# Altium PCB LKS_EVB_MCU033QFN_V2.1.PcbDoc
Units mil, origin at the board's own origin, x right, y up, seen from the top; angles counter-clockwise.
Board outline 2625 x 1560 mil, 2 copper layers (Top Layer, Bottom Layer); 25 components, 32 nets, 124 pads, 23 vias.
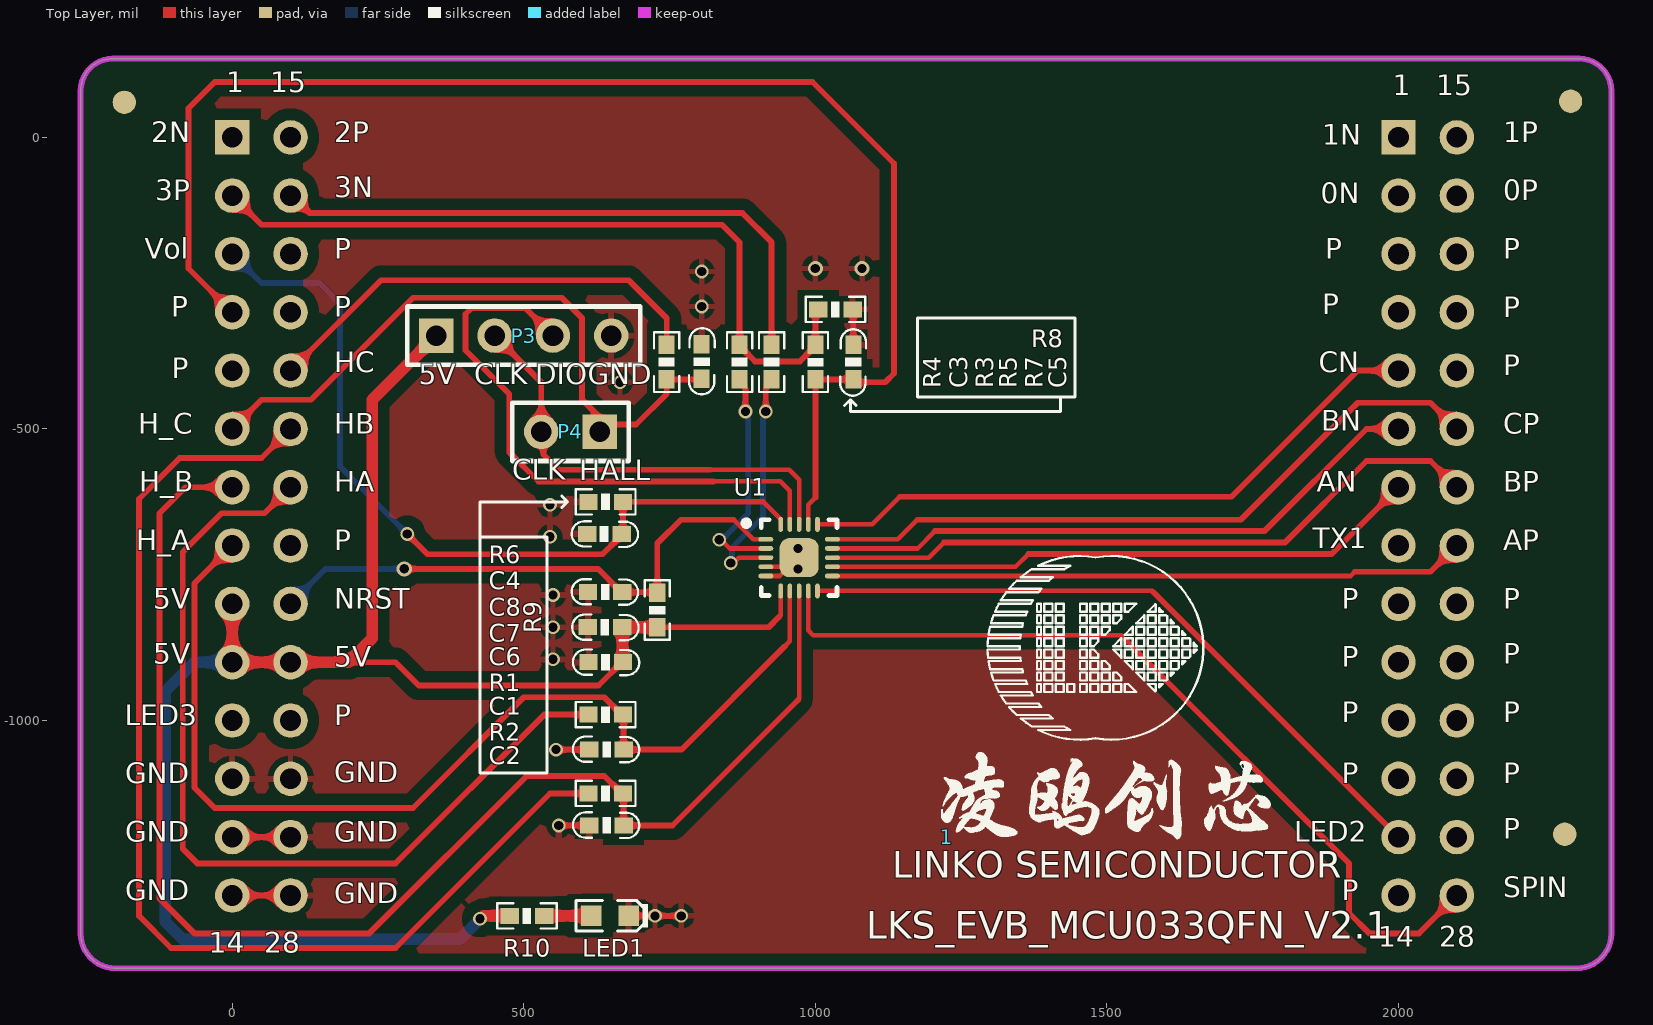
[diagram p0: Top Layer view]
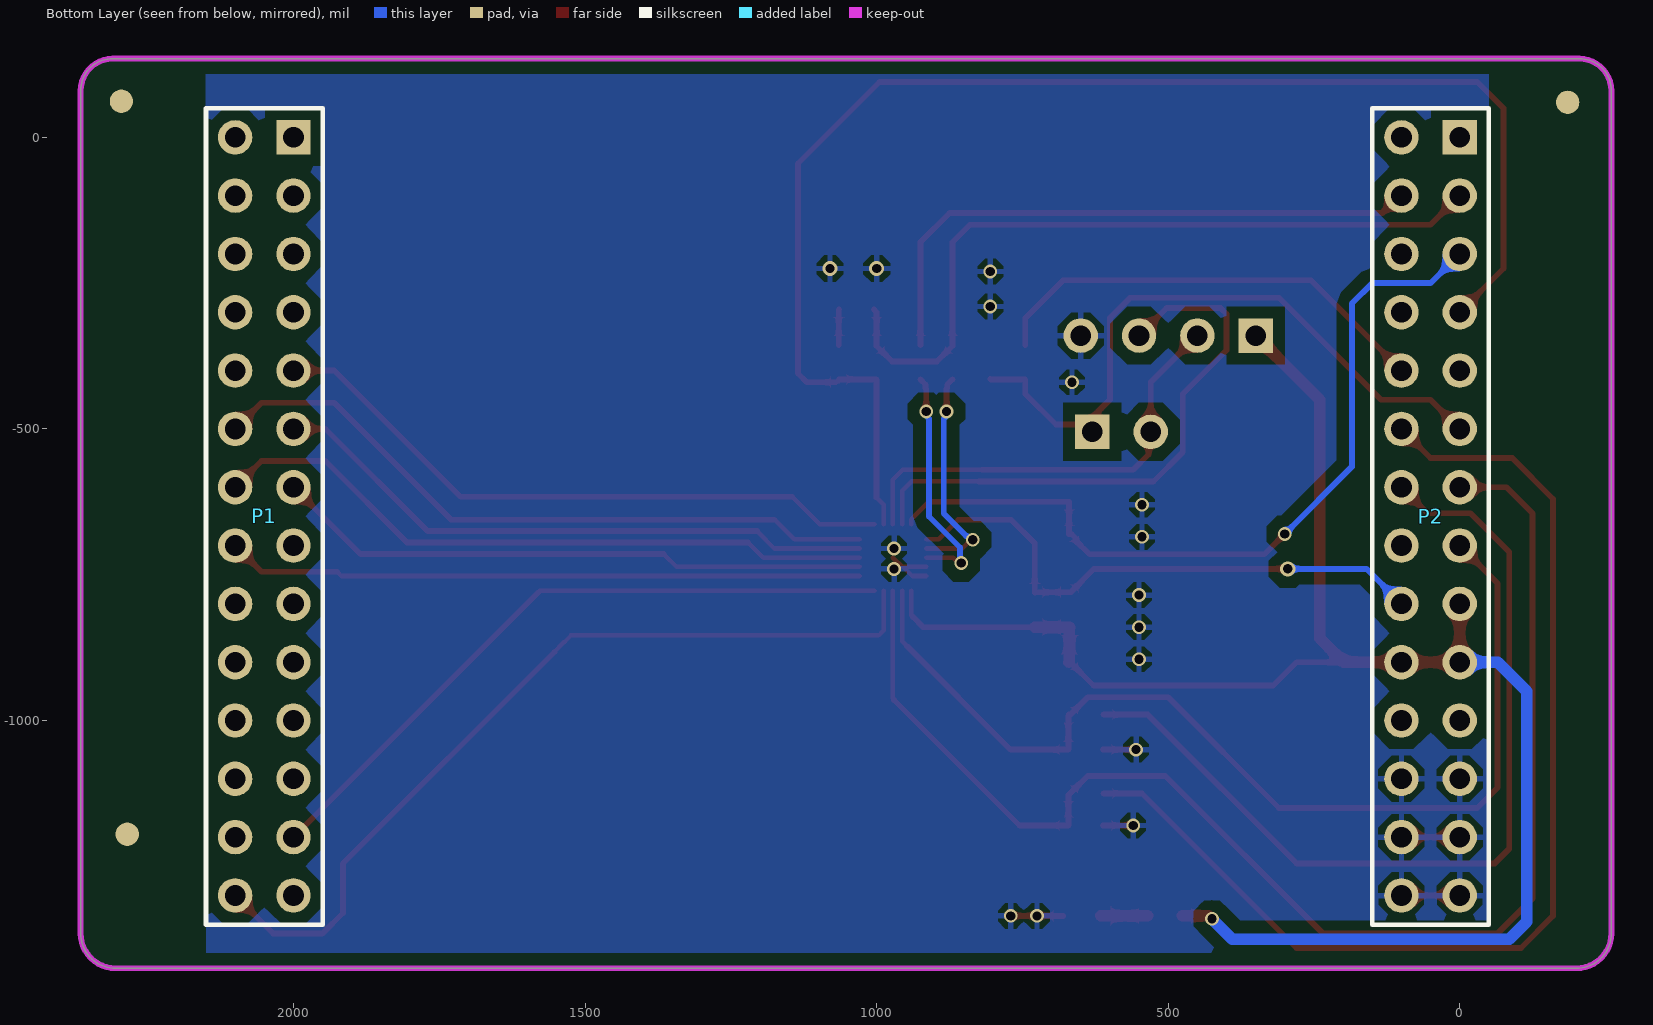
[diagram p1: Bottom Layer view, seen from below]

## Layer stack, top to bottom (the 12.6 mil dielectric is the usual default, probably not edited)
Top Solder: solder mask 0.4, Solder Resist, Dk 3.5
Top Layer: signal copper 1.4
Dielectric 1: dielectric 12.6, FR-4, Dk 4.8
Bottom Layer: signal copper 1.4
Bottom Solder: solder mask 0.4, Solder Resist, Dk 3.5

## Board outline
-260,-1365 ccw(c-200,-1365) -200,-1425 2305,-1425 ccw(c2305,-1365) 2365,-1365 2365,80 ccw(c2310,80) 2310,135 -205,135 ccw(c-205,80) -260,80
cut-out: -2580,-3405 -2570,-3405 -2570,-3395 -2580,-3395

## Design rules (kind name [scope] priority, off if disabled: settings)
Clearance Clearance_2 [InPolygon] p1: gap=20 ignorepadtopadclearanceinfootprint=FALSE
Clearance Clearance_1 [InNet('+5V')] p2: gap=7.87 ignorepadtopadclearanceinfootprint=FALSE
Clearance [All] p3: gap=7.87 ignorepadtopadclearanceinfootprint=FALSE
ComponentClearance [All] p1: gap=0 collisioncheckmode=3 verticalgap=0 showdistances=FALSE
MinimumSolderMaskSliver [All] p1: minsoldermaskwidth=0
PolygonConnect [All] p1: connectstyle=Relief reliefconductorwidth=10 reliefentries=4 polygonreliefangle="90 Angle" airgapwidth=10
RoomDefinition LKS_EVB_MCU033QFN_V2.0 [InComponentClass('LKS_EVB_MCU033QFN_V2.0')] p1: confinementstyle=ConfineIn formatcopy=TRUE lockcomponents=FALSE outline -2580,-3405 -580,-3405 -580,-2405 -2580,-2405
RoutingVias [All] p1: holewidth=28 width=50 viastyle="Through Hole" minholewidth=28 minwidth=50 maxholewidth=28 maxwidth=50
SilkToSilkClearance [All] p1: silktosilkclearance=5
SilkToSolderMaskClearance [IsPad] p1: minsilkscreentomaskgap=5 clearancetoexposedcopper=TRUE
SolderMaskExpansion [All] p1: expansion=4 istentingtop=FALSE
Width [All] p1: maxlimit=100 minlimit=1 preferedwidth=10
26 further rules are at their usual default settings.

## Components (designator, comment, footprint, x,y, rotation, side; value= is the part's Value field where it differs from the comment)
1 "LKS_sign" LKS_LOGO2 1225,-1200 r0 top
C1 "10nF/16V" 0603C 671.18,-1050 r180 top
C2 "10nF/16V" 0603C 671.18,-1180 r180 top
C3 "10nF/16V" 0603C 805,-414.06 r90 top
C4 "100nF/50V" 0603C 608.82,-680 r0 top
C5 "1nF/50V" 0603C 1065,-355.94 r270 top
C6 "10uF/10V" 0603C 610.95,-900 r0 top
C7 "100nF/50V" 0603C 609.77,-840 r0 top
C8 "100nF/50V" 0603C 669.06,-780 r180 top
LED1 "LED" 0603D 647.82,-1335 r0 top
P1 "Header 14X2A" HDR2X14_CEN 2000,0 r270 bottom
P2 "Header 14X2A" HDR2X14_CEN 0,0 r270 bottom
P3 "Header 4" HDR1X4 350,-340 r0 top
P4 "Header 2" HDR1X2 630,-505 r180 top
R1 "2K" 0603R 610.94,-990 r0 top value=K
R2 "2K" 0603R 610.94,-1125 r0 top value=K
R3 "1K1%" 0603R 870,-355.94 r270 top value=K
R4 "2K" 0603R 745,-355.94 r270 top value=K
R5 "1K1%" 0603R 925,-355.94 r270 top value=K
R6 "1K1%" 0603R 610.94,-625 r0 top value=K
R7 "1K1%" 0603R 1000,-415 r90 top value=K
R8 "10R" 0603R 1005,-295 r0 top value=K
R9 "20K1%" 0603R 728.82,-840 r90 top value=K
R10 "3.3K" 0603R 475.94,-1335 r0 top value=330
U1 "LKS033" "QFN20 3x3_M" 972.09,-720.75 r0 top

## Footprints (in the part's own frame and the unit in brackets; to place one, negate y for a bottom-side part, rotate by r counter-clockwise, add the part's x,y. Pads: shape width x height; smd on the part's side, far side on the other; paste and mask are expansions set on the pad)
0603C [mm]
  rect 0.8x0.7 smd: 1(0,0) 2(1.5,0)
  silkscreen extent -0.68,-0.57 2.21,0.55
0603D [mm]
  rect 0.9x0.9 smd: 1(-0.813,0) 2(0.813,0)
  silkscreen extent -1.47,-0.66 1.65,0.66
0603R [mm]
  rect 0.8x0.7 smd: 1(0,0) 2(1.5,0)
  silkscreen extent -0.55,-0.55 2.05,0.55
HDR1X2 [mm] "Connector; Header; 2 Position"
  rect 1.5x1.5 hole 0.9: 1(0,0)
  round 1.5 hole 0.9: 2(2.54,0)
  silkscreen extent -1.27,-1.27 3.81,1.27
HDR1X4 [mm] "Connector; Header; 4 Position"
  rect 1.5x1.5 hole 0.9: 1(0,0)
  round 1.5 hole 0.9: 2(2.54,0) 3(5.08,0) 4(7.62,0)
  silkscreen extent -1.27,-1.27 8.89,1.27
HDR2X14_CEN [mm] "Connector; Header; 14x2 Position"
  rect 1.5x1.5 hole 0.9: 1(0,0)
  round 1.5 hole 0.9: 2(2.54,0) 3(5.08,0) 4(7.62,0) 5(10.16,0) 6(12.7,0) 7(15.24,0) 8(17.78,0) 9(20.32,0) 10(22.86,0) 11(25.4,0) 12(27.94,0) 13(30.48,0) 14(33.02,0) 15(0,-2.54) 16(2.54,-2.54) 17(5.08,-2.54) 18(7.62,-2.54) 19(10.16,-2.54) 20(12.7,-2.54) 21(15.24,-2.54) 22(17.78,-2.54) 23(20.32,-2.54) 24(22.86,-2.54) 25(25.4,-2.54) 26(27.94,-2.54) 27(30.48,-2.54) 28(33.02,-2.54)
  silkscreen extent -1.27,-3.81 34.29,1.27
LKS_LOGO2 [mil] "标?"
  silkscreen extent 70,167 440,482
"QFN20 3x3_M" [mm] "QFN, 20-Leads, Body 3.00x3.00mm, Pitch 0.40mm, Thermal Pad 1.70x1.70mm, IPC Medium Density  QFN40P300X300X60_HS-21N"
  oval 0.65x0.2 smd: 1(-1.45,0.8) 2(-1.45,0.4) 3(-1.45,0) 4(-1.45,-0.4) 5(-1.45,-0.8) 11(1.45,-0.8) 12(1.45,-0.4) 13(1.45,0) 14(1.45,0.4) 15(1.45,0.8)
  oval 0.2x0.65 smd: 6(-0.8,-1.45) 7(-0.4,-1.45) 8(0,-1.45) 9(0.4,-1.45) 10(0.8,-1.45) 16(0.8,1.45) 17(0.4,1.45) 18(0,1.45) 19(-0.4,1.45) 20(-0.8,1.45)
  rrect50% 1.7x1.7 smd: 21(0,0)
  silkscreen extent -2.42,-1.65 1.65,1.65, body extent -1.5,-1.5 1.5,1.5, height 0.6

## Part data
C1 C2 C3: library part CAP, "Capacitor"
C4 C5 C6 C7 C8: library part C, "Capacitor"
LED1: "LED_Light"
P1 P2: "Header, 14-Pin, Dual row"
P3: "Header, 4-Pin"
P4: "Header, 2-Pin"
R1 R2 R3 R4 R5 R6 R7 R8 R9 R10: library part Res, "Resistor"
U1: library part LKS32MC033H6S8_QFN, "CHIP--QFN20"

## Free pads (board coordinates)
  round 40 all layers, no hole: 2(2295,61.86) 3(2285,-1195) 4(-185,60)

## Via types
v1: diameter 23.62, hole 15.75, Top Layer to Bottom Layer, 20 vias
v2: diameter 26, hole 16, Top Layer to Bottom Layer, 3 vias

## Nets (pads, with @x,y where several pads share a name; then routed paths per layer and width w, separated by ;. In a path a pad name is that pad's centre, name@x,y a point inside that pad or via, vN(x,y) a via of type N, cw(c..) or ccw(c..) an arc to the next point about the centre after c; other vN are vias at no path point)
+5V: C6.2 C7.2 P2.9 P2.10 P2.24 P3.1 R9.1 R10.1 U1.6 | length 2958.7
  Top Layer w7.87: 937.4,-822.6 940.59,-819.41 U1.6
  Top Layer w10: 198.98,-900 280,-900 320,-940 628.03,-940 668.03,-900 C6.2 ; R9.1 920,-840 937.4,-822.6
  Top Layer w20: P2.9 P2.10 P2.24 198.98,-900 240,-858.98 240,-450 P3.1 ; v1(425,-1340) 425.98,-1340 430.98,-1335 R10.1 ; C6.2 669.41,-899.41 669.41,-840.59 C7.2 R9.1
  Bottom Layer w20: P2.10 -65,-900 -115,-950 -115,-1345 -85,-1375 390,-1375 v1(425,-1340)
GND: C1.2 C2.2 C3.2 C4.1 C5.1 C6.1 C7.1 C8.2 LED1.2 P2.12 P2.13 P2.14 P2.26 P2.27 P2.28 P3.4 R6.1 R8.2 U1.4 U1.5 U1.21 | length 570.6
  Top Layer w7.87: U1.5 938.92,-752.24 U1.21@954.67,-736.5 ; U1.4 U1.21@954.67,-736.5 ; U1.21 956.34,-736.5 U1.21@954.67,-736.5
  Top Layer w10: P2.14 P2.28 ; P2.13 P2.27 ; v1(555,-1050) C1.2 ; v1(560,-1180) C2.2 ; LED1.2 v1(770,-1335) ; R8.2 1065,-295.95 C5.1
  other v1: 724.91,-1335 550,-895 550,-840 550,-785 970,-740 970,-705 545,-685 545,-630 665,-420 805,-290 805,-230
  other v2: 1000,-225 1080,-225
GND0: P2.16 R5.1 | length 1034.1
  Top Layer w10: P2.16 102.97,-100 132.97,-130 875,-130 925,-180 R5.1
HALL_U: C1.1 P2.8 R1.2 U1.7 | length 1791.4
  Top Layer w7.87: 947.66,-872.66 956.34,-863.98 U1.7
  Top Layer w10: P2.8 -65,-765 -65,-1115 -30,-1150 310,-1150 500,-960 638.03,-960 668.03,-990 R1.2 671.18,-991.18 C1.1 770.32,-1050 947.66,-872.66
HALL_V: C2.1 P2.7 R2.2 U1.8 | length 2378
  Top Layer w7.87: 970,-965 972.09,-962.91 U1.8
  Top Layer w10: P2.7 -80,-600 -125,-645 -125,-1305 -65,-1365 235,-1365 505,-1095 638.03,-1095 671.18,-1128.15 C2.1 755,-1180 970,-965
HALL_W: C3.1 P2.6 P4.1 R4.2 | length 1135.1
  Top Layer w10: P2.6 50,-450 135,-450 310,-275 565,-275 600,-310 600,-450 P4.1@642.5,-492.5 ; P4.1 P4.1@642.5,-492.5 ; C3.1 804.06,-415 R4.2 745,-440 692.5,-492.5 P4.1@642.5,-492.5
HU: P2.21 R1.1 | length 1551.9
  Top Layer w10: P2.21 55.47,-644.53 -18.44,-644.53 -85,-711.08 -85,-1220 -60,-1245 280,-1245 535,-990 R1.1
HV: P2.20 R2.1 | length 1928.2
  Top Layer w10: P2.20 50,-550 -90,-550 -160,-620 -160,-1335 -105,-1390 280,-1390 545,-1125 R2.1
HW: P2.19 R4.1 | length 782.1
  Top Layer w10: P2.19 255,-245 680,-245 745,-310 R4.1
LED2: P1.13 U1.10 | length 1171.3
  Top Layer w7.87: U1.10 1577.83,-777.83 1580,-780
  Top Layer w10: 1580,-780 P1.13
NetLED1_1: LED1.1 R10.2 | length 80.8
  Top Layer w20: R10.2 LED1.1
NRST: C8.1 P2.23 R9.2 U1.1 | length 972.3
  Top Layer w7.87: 860,-655.63 893.62,-689.25 U1.1
  Top Layer w10: v2(295,-740) 627.09,-740 667.09,-780 C8.1 727.88,-780 R9.2 728.82,-696.18 769.37,-655.63 860,-655.63
  Bottom Layer w10: P2.23 160,-740 v2(295,-740)
OC: C5.2 P2.4 R7.1 U1.17 | length 2419.6
  Top Layer w7.87: U1.17 987.83,-630.29 1000,-618.12
  Top Layer w10: P2.4 -75,-225 -75,50 -30,95 995,95 1135,-45 1135,-405 1120,-420 C5.2@1070,-420 ; 1000,-618.12 R7.1 C5.2 C5.2@1065,-416.97
OPA1_IN: R5.2 U1.3 | length 407.8
  Top Layer w7.87: v1(855,-730) 859.26,-730 868.51,-720.75 U1.3
  Top Layer w10: v1(915,-470) 915,-431.61 916.22,-430.39 916.22,-423.78 R5.2
  Bottom Layer w10: v1(855,-730) 856.81,-728.19 856.81,-703.19 910,-650 910,-482.67 912.39,-480.28 912.39,-472.61 v1(915,-470)
OPA1_IP: R3.2 U1.2 | length 391.1
  Top Layer w7.87: v1(835,-690) 838.41,-690 853.41,-705 U1.2
  Top Layer w10: R3.2 878.78,-423.78 878.78,-430.39 880,-431.61 v1(880,-470)
  Bottom Layer w10: v1(835,-690) 838.69,-690 845.14,-683.54 846.46,-683.54 885,-645 885,-482.67 882.61,-480.28 882.61,-472.61 v1(880,-470)
PGND: P2.2 R3.1 R7.2 R8.1 | length 1298.1
  Top Layer w10: P2.2 50,-150 840,-150 870,-180 R3.1 870,-357.91 896.65,-384.57 973.35,-384.57 1000,-357.91 R7.2 1000,-300 R8.1
PGND0: P1.2
PGND1: P1.1
PGND2: P2.1
SPin: P1.28 U1.9 | length 1476.7
  Top Layer w7.87: U1.9 987.83,-845.51 996.49,-854.16 1524.16,-854.16 1535.31,-865.31
  Top Layer w8: 1535.31,-865.31 1552.5,-882.5
  Top Layer w10: 1552.5,-882.5 1915,-1245 1915,-1330 1950,-1365 2035,-1365 P1.28
  Bottom Layer w10: P1.28 P1.28@2100,-1295
SWCLK: P3.2 P4.2 U1.18 | length 757.9
  Top Layer w7.87: 820,-570 955,-570 972.09,-587.09 U1.18
  Top Layer w10: P3.2 530,-420 P4.2@530,-491.61 ; P4.2 533.67,-508.67 533.67,-543.67 560,-570 820,-570
SWDIO: P3.3 U1.19 | length 1008
  Top Layer w7.87: 825,-590 840,-590 940,-590 956.34,-606.34 U1.19
  Top Layer w10: P3.3 502.87,-292.87 410,-292.87 400,-302.87 400,-365 475,-440 475,-540 525,-590 825,-590
UN: P1.7 U1.12 | length 1027.4
  Top Layer w7.87: U1.12 1343.19,-736.5 1365,-714.68
  Top Layer w10: 1365,-714.68 1885.31,-714.68 P1.7
UP: P1.22 U1.11 | length 1092.5
  Top Layer w7.87: U1.11 1917.76,-752.24 1925,-745
  Top Layer w10: 1925,-745 2055,-745 P1.22
UP-: P2.15
VN: P1.6 U1.14 | length 1055.7
  Top Layer w7.87: U1.14 1175.32,-705 1205,-675.32
  Top Layer w10: 1205,-675.32 1769.69,-675.32 1945,-500 P1.6
Vol_ADC: C4.2 P2.3 R6.2 U1.20 | length 1411
  Top Layer w7.87: 910,-625 910.79,-625 940.59,-654.8 U1.20
  Top Layer w10: v1(300,-680) 335,-715 635,-715 657.13,-692.87 657.13,-688.78 665.91,-680 670,-680 R6.2 910,-625
  Bottom Layer w10: P2.3 50,-250 150,-250 185,-285 185,-565 v1(300,-680)
VP: P1.21 U1.13 | length 1158.1
  Top Layer w7.87: U1.13 1194.25,-720.75 1220,-695
  Top Layer w10: 1220,-695 1805,-695 1945,-555 2055,-555 P1.21
VP-: P1.15
WN: P1.5 U1.16 | length 1105.6
  Top Layer w7.87: U1.16 1097.6,-663.66 1145,-616.26
  Top Layer w10: 1145,-616.26 1713.74,-616.26 1930,-400 P1.5
WP: P1.20 U1.15 | length 1186.5
  Top Layer w7.87: U1.15 1141.38,-689.25 1175,-655.63
  Top Layer w10: 1175,-655.63 1729.37,-655.63 1930,-455 2055,-455 P1.20
WP-: P1.16
pads on no net: P1.3 P1.4 P1.8 P1.9 P1.10 P1.11 P1.12 P1.14 P1.17 P1.18 P1.19 P1.23 P1.24 P1.25 P1.26 P1.27 P2.5 P2.11 P2.17 P2.18 P2.22 P2.25

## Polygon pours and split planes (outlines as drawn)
GND on Bottom Layer "GND_L02_P000" (solid, remove dead copper, pour order 0): -50,128.77 -50,-1425 2150,-1425 2150,134.58
GND on Top Layer "GND_L01_P005" (solid, remove dead copper, pour order 5): -50,-1425 2150,-1425 2150,135 -50,135

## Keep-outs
Keep-Out Layer:
  the board outline again, w10

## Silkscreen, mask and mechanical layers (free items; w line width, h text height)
Top Overlay:
  drawing of 26 lines, arcs and shapes, not listed
  text "2N" at -138.73,-20 h60
  text "2P" at 175,-20 h60
  text "1P" at 2180,-20 h60
  text "1N" at 1869.55,-25 h60
  text "3N" at 174.94,-115 h60
  text "3P" at -131.62,-120 h60
  text "0P" at 2179.94,-120 h60
  text "0N" at 1866.83,-125 h60
  text "Vol" at -149.61,-220 h60
  text "P" at 175,-220 h60
  text "P" at 1874.54,-220 h60
  text "P" at 2180,-220 h60
  text "P" at 1869.27,-315 h60
  text "P" at -105,-320 h60
  text "P" at 175,-320 h60
  text "P" at 2180,-320.67 h60
  text "HC" at 175,-415 h60
  text "CN" at 1863.33,-415 h60
  text "P" at 2180,-420 h60
  text "P" at -103.71,-425 h60
  text "5V" at 320,-435 h60
  text "CLK" at 415,-435 h60
  text "DIO" at 520,-435 h60
  text "GND" at 610,-435 h60
  text "BN" at 1867.44,-515 h60
  text "H_C" at -161.26,-520 h60
  text "HB" at 175,-520 h60
  text "CP" at 2180,-520 h60
  text "CLK" at 480.06,-599.45 h60
  text "HALL" at 595.06,-600 h60
  text "H_B" at -159.43,-620 h60
  text "HA" at 175,-620 h60
  text "AN" at 1860,-620 h60
  text "BP" at 2180,-620 h60
  text "TX1" at 1852.62,-716.98 h60
  text "H_A" at -164.7,-720 h60
  text "P" at 175,-720 h60
  text "AP" at 2179.94,-720 h60
  text "5V" at -135.4,-820 h60
  text "NRST" at 175,-820 h60
  text "P" at 1902.51,-820 h60
  text "P" at 2180,-820 h60
  text "5V" at -135.4,-915 h60
  text "P" at 2180,-915 h60
  text "5V" at 174.94,-920 h60
  text "P" at 1902.51,-920 h60
  text "P" at 1902.51,-1015 h60
  text "P" at 2180,-1015 h60
  text "LED3" at -183.91,-1020 h60
  text "P" at 175,-1020 h60
  text "GND" at 175,-1118.3 h60
  text "GND" at -183.07,-1120 h60
  text "P" at 1902.51,-1120 h60
  text "P" at 2179.94,-1120 h60
  text "P" at 2180,-1215 h60
  text "GND" at -183.07,-1220 h60
  text "GND" at 175,-1220 h60
  text "LED2" at 1821.32,-1220 h60
  text "SPIN" at 2180,-1315 h60
  text "GND" at -183.07,-1320 h60
  text "P" at 1902.51,-1320 h60
  text "GND" at 175,-1325 h60
  text "LKS_EVB_MCU033QFN_V2.1" at 1087.5,-1390 h80
Top Solder:
  circle w78: c2285,-1195 r17
  circle w78: c-185,60 r17
  circle w78: c2295,61.86 r17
